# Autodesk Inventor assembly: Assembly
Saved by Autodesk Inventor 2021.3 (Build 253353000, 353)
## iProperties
Created: 2022-04
Part Number: Assembly
Document SubType Name: Assembly
Designer: Administrator
Title: Assembly v24
Author: Administrator
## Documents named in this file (7)
- c:\worker\convert-fusion-r02\tmp\job-1\57\output\files\f9e42cba-e390-44b0-9630-f24d5638462a\713f7286-bf71-42bd-8bc6-5eea6ff0c9e9.iam
- c:\worker\convert-fusion-r02\tmp\job-1\57\output\files\f9e42cba-e390-44b0-9630-f24d5638462a\FR07-H101K v5.iam
- c:\worker\convert-fusion-r02\tmp\job-1\57\output\files\f9e42cba-e390-44b0-9630-f24d5638462a\Base v10.iam
- c:\worker\convert-fusion-r02\tmp\job-1\57\output\files\f9e42cba-e390-44b0-9630-f24d5638462a\91290A010_Black-Oxide Alloy Steel Socket Head Screw v2.iam
- c:\worker\convert-fusion-r02\tmp\job-1\57\output\files\f9e42cba-e390-44b0-9630-f24d5638462a\91290A010_Black-Oxide Alloy Steel Socket Head Screw v2_1.iam
- c:\worker\convert-fusion-r02\tmp\job-1\57\output\files\f9e42cba-e390-44b0-9630-f24d5638462a\Pole v12.iam
- c:\worker\convert-fusion-r02\tmp\job-1\57\output\files\f9e42cba-e390-44b0-9630-f24d5638462a\Extension v24.iam
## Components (6 placed, 5 different names)
1. FR07-H101K v5:1 [sub-assembly]
2. Base v10:1 [sub-assembly]
3. 91290A010_Black-Oxide Alloy Steel Socket Head Screw v2:1 [sub-assembly]
4. 91290A010_Black-Oxide Alloy Steel Socket Head Screw v2:2 [sub-assembly]
5. Pole v12:1 [sub-assembly]
6. Extension v24:1 [sub-assembly]
